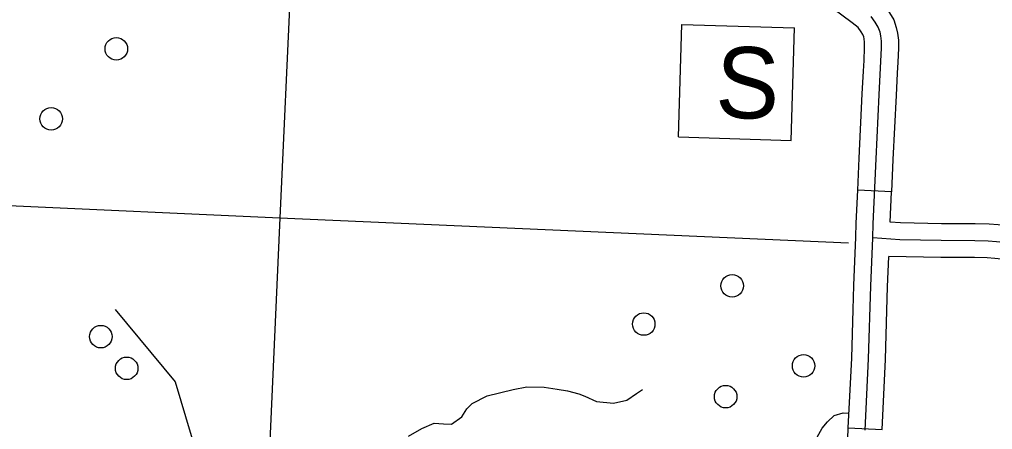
# Model space of a CAD drawing. Extents: x 653372 to 905732, y 627442 to 787275.
# Drawn here: x 709737 to 714058, y 756322 to 758143 of the extents above; entities that cross this region are included whole.
import ezdxf

# ---------------------------------------------------------------- set-up
doc = ezdxf.new("R2010")
doc.units = 0
for name, color, linetype in [('31', 7, 'Continuous'), ('35', 7, 'Continuous'), ('45', 7, 'Continuous'), ('5', 7, 'Continuous'), ('56', 7, 'Continuous'), ('57', 7, 'Continuous')]:
    doc.layers.add(name, color=color, linetype=linetype)

msp = doc.modelspace()

# ---------------------------------------------------------------- linework, layer by layer
at = {"layer": '31'}
for p, q in [((713609.4, 757377.6), (713459.5, 757384.2)), ((713417.4, 756329.5), (713567.3, 756322.1))]:
    msp.add_line(p, q, dxfattribs=at)
for points in [[(713366.1, 758375.9), (713381.2, 758359.5), (713400.2, 758341), (713419.3, 758326.1), (713443.7, 758307.8), (713478.6, 758282.6), (713524.9, 758247.2), (713559.9, 758221.1), (713576.4, 758204.6), (713599.9, 758171.5), (713619.1, 758140.8), (713630.6, 758106.8), (713636.4, 758082.3), (713639.8, 758051.1), (713640.2, 758014.5), (713637.7, 757953.4), (713634.9, 757904.1)], [(713485.1, 757912.4), (713487.8, 757960.6), (713490.1, 758016.7), (713489.8, 758042.2), (713488.3, 758056.8), (713486.2, 758065.4), (713482.6, 758076.3), (713475.1, 758088.2), (713461.4, 758107.4), (713434.5, 758127.5), (713389.1, 758162.1), (713354.6, 758187.1), (713328.1, 758207), (713301.4, 758227.8), (713273.6, 758255), (713255.9, 758274.1)], [(713540.8, 757524), (713554.5, 757808.3), (713562.7, 757957), (713565.1, 758015.6), (713564.8, 758046.6), (713562.3, 758069.5), (713558.4, 758086.1), (713550.8, 758108.5), (713537.5, 758129.9), (713518.9, 758156)], [(713459.5, 757384.2), (713465.9, 757527.5), (713479.6, 757812.2), (713485.1, 757912.4)], [(713634.9, 757904.1), (713629.4, 757804.4), (713615.7, 757520.5), (713609.4, 757377.6)], [(713492, 756318.9), (713507.7, 756636.1), (713517, 756958.2), (713525.8, 757173.6), (713528, 757235.1), (713540.8, 757524)], [(713439, 756855.5), (713442.1, 756960.8), (713450.9, 757176.4), (713453.1, 757238.1), (713459.5, 757384.2)], [(713603.5, 757242.8), (713609.4, 757377.6)], [(713956.8, 757235.6), (713830.6, 757236), (713649.5, 757239.3), (713603.5, 757242.8)], [(714490.5, 757157.5), (714444.3, 757165.6), (714362.8, 757185.2), (714303.2, 757198.7), (714246.7, 757208.7), (714205.4, 757215.3), (714174.6, 757219.2), (714129.8, 757225), (714083.2, 757230.6), (714042.7, 757233.7), (713980.6, 757235.5), (713956.8, 757235.6)], [(714558.8, 757077), (714532.7, 757075.4), (714503.3, 757079.1), (714429, 757092.1), (714345.7, 757112.2), (714288.4, 757125.2), (714234.3, 757134.8), (714194.9, 757141), (714165, 757144.8), (714120.5, 757150.6), (714076, 757155.9), (714038.7, 757158.7), (713979.3, 757160.5), (713829.8, 757161), (713646, 757164.3), (713525.8, 757173.6)], [(713588.9, 756851.1), (713592, 756955.5), (713597.5, 757090.1)], [(713956.2, 757085.6), (713829, 757086.1), (713597.5, 757090.1)], [(714464.6, 757009.8), (714413.8, 757018.6), (714328.6, 757039.1), (714273.5, 757051.7), (714221.9, 757060.8), (714184.4, 757066.8), (714155.5, 757070.4), (714111.2, 757076.2), (714068.7, 757081.3), (714034.8, 757083.8), (713978.1, 757085.5), (713956.2, 757085.6)], [(713417.4, 756329.5), (713432.7, 756639), (713439, 756855.5)], [(713567.3, 756322.1), (713582.6, 756633.2), (713588.9, 756851.1)], [(713323.6, 755939.5), (713359.7, 755951.2), (713384.7, 755962.7), (713392, 755969.6), (713393.6, 755972.4), (713398.1, 755990.4), (713405.4, 756060.5), (713409, 756157.1), (713417.1, 756322.6), (713417.4, 756329.5)]]:
    msp.add_lwpolyline(points, dxfattribs=at)
at = {"layer": '35'}
msp.add_lwpolyline([(711464.9, 756292.3), (711523.8, 756326.4), (711578.4, 756350.7), (711620.2, 756347.5), (711656.1, 756346.4), (711701, 756379), (711724, 756414.3), (711746.7, 756437.5), (711813.6, 756471.5), (711929.8, 756499.8), (711990, 756512), (712067.8, 756509.6), (712125.5, 756501.9), (712171.2, 756494.6), (712220.7, 756481.1), (712248.3, 756470.3), (712299.5, 756446.8), (712374.3, 756438.6), (712434.6, 756452.7), (712477.4, 756481.4), (712503.3, 756499.6)], dxfattribs=at)
at = {"layer": '45'}
msp.add_lwpolyline([(713152.3, 756239.7), (713231.6, 756234.6), (713232.5, 756234.8), (713234.1, 756235.5), (713242.5, 756242), (713271.9, 756274.8), (713300.8, 756328.5), (713325.3, 756355.6), (713354.7, 756384.7), (713394.8, 756395.8), (713420.7, 756394.4)], dxfattribs=at)
at = {"layer": '5'}
for points in [[(710942.4, 758325.4), (710892.9, 757262.5)], [(709657.1, 757318), (710892.9, 757262.5)], [(710892.9, 757262.5), (710750.3, 754053.8)], [(710892.9, 757262.5), (713419.1, 757150.9)]]:
    msp.add_lwpolyline(points, dxfattribs=at)
at = {"layer": '56'}
msp.add_lwpolyline([(710162.4, 756855), (710429.3, 756534.3), (710688, 755665.3)], dxfattribs=at)
for centre in [(710167.4, 758012.4), (709878.3, 757701.7), (712902.1, 756959.9), (712509.2, 756790.4), (710098.7, 756734.4), (710213.4, 756593.8), (713219.1, 756604.5), (712872.9, 756468.1)]:
    msp.add_circle(centre, 50, dxfattribs=at)
at = {"layer": '57'}
for p, q in [((712664, 757620.8), (712679, 758120.6)), ((712679, 758120.6), (713178.8, 758105.6)), ((713163.8, 757605.8), (713178.8, 758105.6)), ((712664, 757620.8), (713163.8, 757605.8))]:
    msp.add_line(p, q, dxfattribs=at)

# ---------------------------------------------------------------- texts
msp.add_text('S', height=316.8, rotation=358.28, dxfattribs=at).set_placement((712824.5, 757707.6))

doc.saveas('drawing.dxf')
